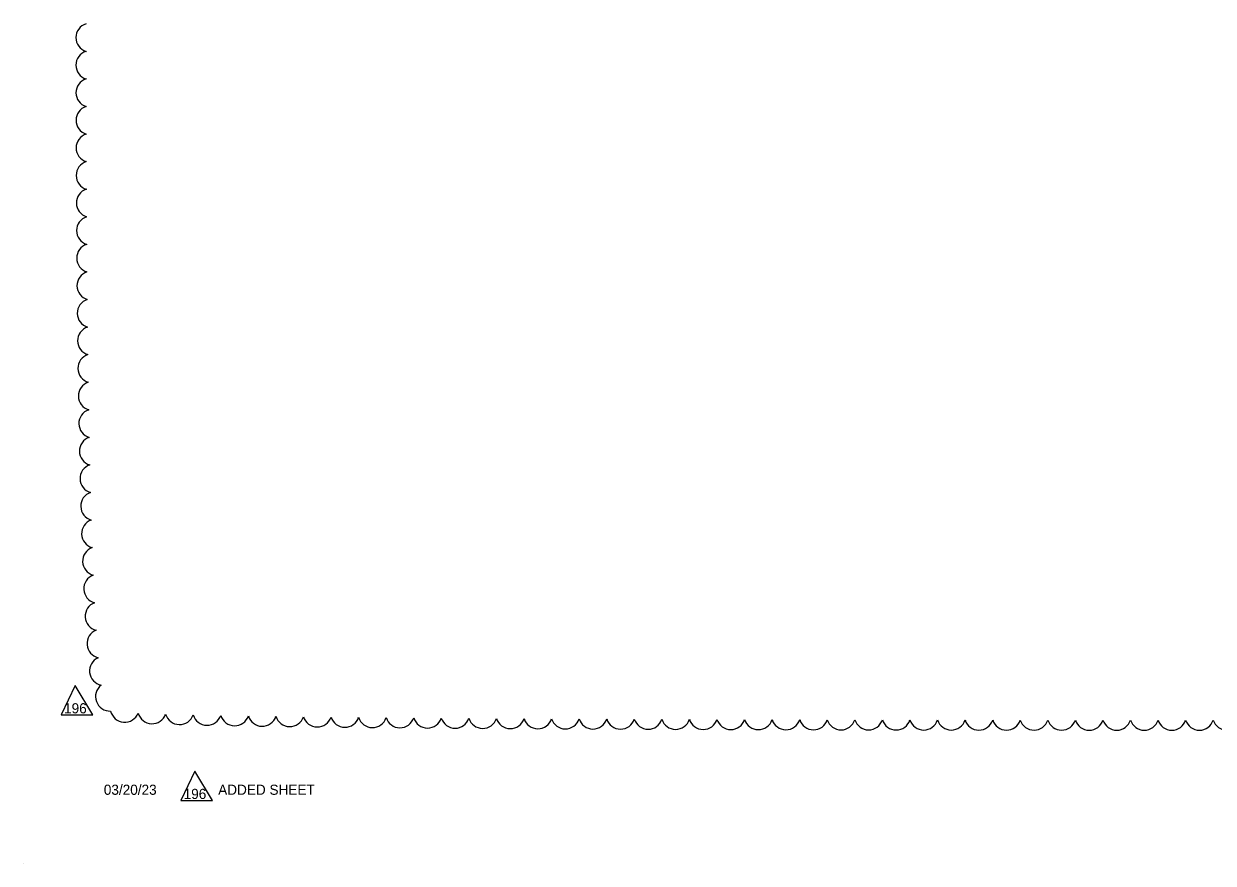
# Model space of a CAD drawing. Extents: x -811 to 10319, y -2309 to 9962.
# Drawn here: x -811.34 to -803.18, y -2271.13 to -2265.38 of the extents above; entities that cross this region are included whole.
import ezdxf

# ---------------------------------------------------------------- set-up
doc = ezdxf.new("R2010")
doc.units = 0
doc.layers.add('ScratchEle_dp', color=7, linetype='Continuous')
doc.layers.add('SheetBorder_dp', color=7, linetype='Continuous')

msp = doc.modelspace()

# ---------------------------------------------------------------- linework, layer by layer
at = {"layer": 'ScratchEle_dp'}
for points in [[(-810.9836, -2269.9151), (-811.0784, -2270.1158), (-810.8622, -2270.1158)], [(-810.1638, -2270.5019), (-810.2586, -2270.7026), (-810.0424, -2270.7026)]]:
    msp.add_lwpolyline(points, close=True, dxfattribs=at)
for centre, start, end in [((-810.8794, -2265.4725), 107.52584, 252.52584), ((-810.8792, -2265.6615), 107.56719, 252.56719), ((-810.8789, -2265.8505), 107.61129, 252.61129), ((-810.8785, -2266.0394), 107.65843, 252.65843), ((-810.8779, -2266.2284), 107.709, 252.709), ((-810.8771, -2266.4174), 107.76343, 252.76343), ((-810.8761, -2266.6063), 107.82224, 252.82224), ((-810.8749, -2266.7953), 107.88605, 252.88605), ((-810.8736, -2266.9843), 107.95561, 252.95561), ((-810.8719, -2267.1732), 108.03183, 253.03183), ((-810.87, -2267.3622), 108.11586, 253.11586), ((-810.8679, -2267.5511), 108.20912, 253.20912), ((-810.8653, -2267.74), 108.31345, 253.31345), ((-810.8625, -2267.929), 108.43121, 253.43121), ((-810.8592, -2268.1179), 108.56556, 253.56556), ((-810.8554, -2268.3067), 108.72081, 253.72081), ((-810.8511, -2268.4956), 108.903, 253.903), ((-810.8461, -2268.6844), 109.12096, 254.12096), ((-810.8403, -2268.8732), 109.38818, 254.38818), ((-810.8335, -2269.0619), 109.72657, 254.72657), ((-810.8255, -2269.2505), 110.17469, 255.17469), ((-810.8156, -2269.4389), 110.80877, 255.80877), ((-810.8031, -2269.6269), 111.80931, 256.80931), ((-810.7858, -2269.8141), 113.77584, 258.77584), ((-810.7447, -2269.9899), 127.48462, 272.48462), ((-810.644, -2270.0663), 193.17348, 338.17348), ((-810.4565, -2270.0769), 195.39639, 340.39639), ((-810.2679, -2270.0828), 195.97806, 340.97806), ((-810.0791, -2270.0874), 196.28744, 341.28744), ((-809.8902, -2270.091), 196.48754, 341.48754), ((-809.7013, -2270.0941), 196.63065, 341.63065), ((-809.5124, -2270.0968), 196.73959, 341.73959), ((-809.3235, -2270.0992), 196.8261, 341.8261), ((-809.1345, -2270.1013), 196.89697, 341.89697), ((-808.9455, -2270.1032), 196.95641, 341.95641), ((-808.7566, -2270.1049), 197.0072, 342.0072), ((-808.5676, -2270.1064), 197.05125, 342.05125), ((-808.3786, -2270.1078), 197.08993, 342.08993), ((-808.1897, -2270.1091), 197.12425, 342.12425), ((-808.0007, -2270.1103), 197.15498, 342.15498), ((-807.8117, -2270.1114), 197.18269, 342.18269), ((-807.6227, -2270.1124), 197.20786, 342.20786), ((-807.4337, -2270.1134), 197.23085, 342.23085), ((-807.2447, -2270.1142), 197.25195, 342.25195), ((-807.0557, -2270.115), 197.27142, 342.27142), ((-806.8667, -2270.1157), 197.28945, 342.28945), ((-806.6778, -2270.1164), 197.30621, 342.30621), ((-806.4888, -2270.117), 197.32184, 342.32184), ((-806.2998, -2270.1176), 197.33647, 342.33647), ((-806.1108, -2270.1181), 197.3502, 342.3502), ((-805.9218, -2270.1186), 197.36311, 342.36311), ((-805.7328, -2270.119), 197.37529, 342.37529), ((-805.5438, -2270.1194), 197.3868, 342.3868), ((-805.3548, -2270.1197), 197.3977, 342.3977), ((-805.1658, -2270.1201), 197.40804, 342.40804), ((-804.9768, -2270.1203), 197.41787, 342.41787), ((-804.7878, -2270.1206), 197.42723, 342.42723), ((-804.5988, -2270.1208), 197.43616, 342.43616), ((-804.4098, -2270.121), 197.44468, 342.44468), ((-804.2208, -2270.1212), 197.45283, 342.45283), ((-804.0318, -2270.1213), 197.46064, 342.46064), ((-803.8428, -2270.1214), 197.46812, 342.46812), ((-803.6538, -2270.1215), 197.4753, 342.4753), ((-803.4648, -2270.1216), 197.4822, 342.4822), ((-803.2759, -2270.1217), 197.48884, 342.48884), ((-803.0869, -2270.1217), 197.49523, 342.49523)]:
    msp.add_arc(centre, 0.0991, start, end, dxfattribs=at)
at = {"layer": 'SheetBorder_dp'}
msp.add_line((-811.3358, -2271.1322), (-811.3358, -2271.1322), dxfattribs=at)

# ---------------------------------------------------------------- texts
at = {"layer": 'ScratchEle_dp'}
for s, p in [('196', (-811.0596, -2270.1051)), ('03/20/23', (-810.7871, -2270.6633)), ('ADDED SHEET', (-810.003, -2270.6633)), ('196', (-810.2398, -2270.6919))]:
    msp.add_text(s, height=0.0696, dxfattribs=at).set_placement(p)

doc.saveas('drawing.dxf')
